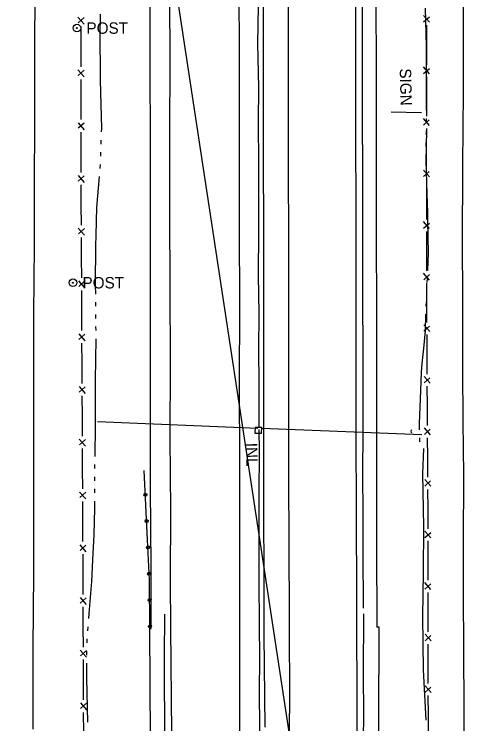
# Model space of a CAD drawing. Extents: x 589250 to 1188077, y 162953 to 363065.
# Drawn here: x 593915.1 to 594159.9, y 176311.4 to 176684.2 of the extents above; entities that cross this region are included whole.
import ezdxf

# ---------------------------------------------------------------- set-up
doc = ezdxf.new("R2010")
doc.units = 0
for name, color, linetype in [('E_BMGRD_P', 7, 'Continuous'), ('E_DRN', 7, 'Continuous'), ('E_DRN_Pipe', 7, 'Continuous'), ('E_DRN_SS_UG', 7, 'Continuous'), ('E_DRN_Text', 7, 'Continuous'), ('E_FEN_P', 7, 'Continuous'), ('E_MISCPROP', 7, 'Continuous'), ('E_RDWY', 7, 'Continuous'), ('E_RDWY_Gravel', 7, 'Continuous'), ('E_SGN', 7, 'Continuous'), ('E_SGN_Text', 7, 'Continuous'), ('E_WAL', 7, 'Continuous'), ('E_WTR_FlowLine', 7, 'Continuous')]:
    doc.layers.add(name, color=color, linetype=linetype)

msp = doc.modelspace()

# ---------------------------------------------------------------- linework, layer by layer
at = {"layer": 'E_BMGRD_P'}
for p, q in [((593985.24, 176408.17), (593983.43, 176444.48)), ((593986.13, 176387.05), (593985.24, 176408.17)), ((593986.43, 176361.44), (593986.13, 176387.05))]:
    msp.add_line(p, q, dxfattribs=at)
for centre, major_axis, ratio in [((593984.06, 176431.8), (0.049, -0.805), 0.932546), ((593984.06, 176431.8), (0.025, -0.406), 0.932546), ((593984.75, 176417.97), (0.049, -0.805), 0.932546), ((593984.75, 176417.97), (0.025, -0.406), 0.932546), ((593985.41, 176404.13), (0.054, -0.805), 0.93253), ((593985.41, 176404.13), (0.027, -0.406), 0.93253), ((593985.99, 176390.29), (0.054, -0.805), 0.93253), ((593985.99, 176390.29), (0.027, -0.406), 0.93253), ((593986.25, 176376.45), (0.051, -0.805), 0.932542), ((593986.25, 176376.45), (0.025, -0.406), 0.932542), ((593986.42, 176362.6), (0.051, -0.805), 0.932542), ((593986.42, 176362.6), (0.025, -0.406), 0.932542)]:
    msp.add_ellipse(centre, major_axis=major_axis, ratio=ratio, dxfattribs=at)
at = {"layer": 'E_DRN'}
for p, q in [((594041.72, 176467.16), (594041.59, 176464.19)), ((594045.23, 176467.01), (594041.72, 176467.16)), ((594045.1, 176464.05), (594045.23, 176467.01)), ((594041.59, 176464.19), (594045.1, 176464.05))]:
    msp.add_line(p, q, dxfattribs=at)
msp.add_arc((594124.58, 176465.03), 0.951, 123.209, 229.4692, dxfattribs=at)
at = {"layer": 'E_DRN_Pipe'}
msp.add_line((594159.86, 175649.53), (593883.52, 177463.68), dxfattribs=at)
for points in [[(594097.87, 176869.17), (594097.7, 176846.21), (594097.91, 176822.26), (594097.93, 176797.28), (594097.77, 176779.42), (594097.83, 176761.39), (594097.7, 176742.5), (594097.95, 176721.78), (594098.08, 176697.67), (594098.04, 176672.95), (594097.93, 176651.09), (594097.96, 176628.52), (594098.17, 176602.72), (594098.15, 176579.66), (594098.22, 176557.12), (594098.25, 176534.43), (594098.28, 176507.45), (594098.28, 176487.3), (594098.37, 176465.05), (594098.21, 176442.71), (594098.39, 176421.74), (594098.44, 176402.02), (594098.56, 176372.17)], [(594042.61, 176764.33), (594042.66, 176762.08), (594042.86, 176743.94), (594043.31, 176721.62), (594043.28, 176707.53), (594043.36, 176688.63), (594042.95, 176668.69), (594043.52, 176645.78), (594043.25, 176627.63), (594043.48, 176605.24), (594043.45, 176590.6), (594043.51, 176570.12), (594043.26, 176547.09), (594043.67, 176526.6), (594043.49, 176508.41), (594043.6, 176489.67), (594043.62, 176471.63), (594043.67, 176467.31)], [(593994.11, 176369), (593993.98, 176346.56), (593993.99, 176331.82), (593994.17, 176314.67), (593994.25, 176292.54), (593994.15, 176275.69), (593994.42, 176254.71), (593994.42, 176231.83), (593994.49, 176213.17), (593994.3, 176195.64), (593994.4, 176168.84), (593994.74, 176145.96), (593994.45, 176124.58), (593994.62, 176098.63), (593994.59, 176075.14), (593994.15, 176056.15), (593994.89, 176029.41), (593994.77, 176002.81)], [(594098.63, 176369.17), (594098.56, 176337.66), (594098.72, 176316.3), (594098.38, 176289.66), (594098.8, 176267.67), (594098.77, 176247.92), (594098.81, 176225.2), (594098.76, 176203.17), (594098.75, 176181.09), (594098.75, 176158.95), (594098.97, 176132.32), (594098.97, 176114.04), (594099.06, 176093.75), (594099.1, 176076.01), (594098.98, 176058.16), (594099.23, 176036.17)]]:
    msp.add_lwpolyline(points, dxfattribs=at)
at = {"layer": 'E_DRN_SS_UG'}
for p, q in [((594043.09, 176466.6), (593958.87, 176470.03)), ((594129.31, 176463.19), (594045.09, 176466.62))]:
    msp.add_line(p, q, dxfattribs=at)
msp.add_lwpolyline([(594043.68, 176466.02), (594043.81, 176454.35), (594043.61, 176431.93), (594043.68, 176409.33), (594043.62, 176386.16), (594043.86, 176363.78), (594043.96, 176345.88), (594043.8, 176328), (594043.97, 176309.66), (594044, 176291.49), (594043.78, 176268.84), (594043.9, 176218.3), (594043.83, 176199.66), (594044.05, 176176.8), (594043.89, 176156.39), (594043.91, 176137.72), (594044.02, 176118.48), (594044.18, 176091.52), (594044.19, 176072.96), (594044.24, 176067.55)], dxfattribs=at)
at = {"layer": 'E_FEN_P'}
for p, q in [((593948.58, 176682.63), (593951.8, 176678.94)), ((593951.79, 176682.46), (593948.65, 176679.68)), ((594133.44, 176679.98), (594130.3, 176683.58)), ((594130.3, 176680.14), (594133.38, 176682.85)), ((593950.07, 176677.71), (593950.08, 176667.12)), ((594131.98, 176668.04), (594131.99, 176678.39)), ((593950.08, 176667.12), (593950.09, 176656.54)), ((594131.97, 176657.7), (594131.98, 176668.04)), ((594130.27, 176653.06), (594133.35, 176655.77)), ((594133.41, 176652.89), (594130.28, 176656.5)), ((593948.61, 176654.91), (593951.83, 176651.23)), ((593951.82, 176654.75), (593948.68, 176651.97)), ((593950.1, 176649.99), (593950.11, 176639.41)), ((594131.95, 176640.96), (594131.96, 176651.3)), ((594131.94, 176630.62), (594131.95, 176640.96)), ((593950.11, 176639.41), (593950.12, 176628.83)), ((594133.38, 176625.8), (594130.25, 176629.41)), ((593948.64, 176627.2), (593951.86, 176623.52)), ((593951.85, 176627.04), (593948.71, 176624.26)), ((594130.25, 176625.97), (594133.32, 176628.68)), ((593950.13, 176622.28), (593950.14, 176611.7)), ((594131.92, 176613.87), (594131.93, 176624.21)), ((593950.14, 176611.7), (593950.15, 176601.12)), ((594131.91, 176606.05), (594131.92, 176613.87)), ((594131.92, 176603.53), (594131.91, 176606.05)), ((593948.67, 176599.49), (593951.89, 176595.81)), ((593951.88, 176599.32), (593948.74, 176596.55)), ((594133.38, 176598.72), (594130.23, 176602.32)), ((594130.24, 176598.88), (594133.31, 176601.6)), ((594131.95, 176586.79), (594131.93, 176597.13)), ((593950.16, 176594.57), (593950.17, 176590)), ((593950.17, 176590), (593950.19, 176583.99)), ((594131.97, 176576.44), (594131.95, 176586.79)), ((593950.19, 176583.99), (593950.24, 176573.41)), ((594133.43, 176571.64), (594130.29, 176575.23)), ((594130.3, 176571.79), (594133.36, 176574.51)), ((593948.77, 176571.77), (593952, 176568.1)), ((593951.98, 176571.62), (593948.85, 176568.83)), ((594132.01, 176559.7), (594131.99, 176570.04)), ((593950.27, 176566.86), (593950.32, 176556.28)), ((594132.03, 176549.36), (594132.01, 176559.7)), ((593950.32, 176556.28), (593950.37, 176545.7)), ((594133.49, 176544.55), (594130.34, 176548.15)), ((594130.35, 176544.71), (594133.42, 176547.42)), ((593948.9, 176544.06), (593952.12, 176540.39)), ((593952.11, 176543.91), (593948.98, 176541.12)), ((594132.06, 176532.61), (594132.04, 176542.96)), ((593950.4, 176539.15), (593950.45, 176528.57)), ((594132.08, 176522.27), (594132.06, 176532.61)), ((593950.45, 176528.57), (593950.5, 176517.98)), ((594133.54, 176517.46), (594130.4, 176521.06)), ((594130.41, 176517.62), (594133.47, 176520.34)), ((593949.03, 176516.35), (593952.25, 176512.68)), ((593952.24, 176516.2), (593949.11, 176513.41)), ((594132.17, 176505.53), (594132.1, 176515.87)), ((593950.53, 176511.43), (593950.58, 176500.85)), ((594132.23, 176495.19), (594132.17, 176505.53)), ((593950.58, 176500.85), (593950.63, 176490.27)), ((594133.71, 176490.38), (594130.55, 176493.97)), ((594130.57, 176490.53), (594133.63, 176493.26)), ((593949.16, 176488.64), (593952.38, 176484.97)), ((593952.37, 176488.48), (593949.24, 176485.7)), ((594132.33, 176478.44), (594132.27, 176488.78)), ((593950.66, 176483.72), (593950.72, 176473.14)), ((594132.4, 176468.1), (594132.33, 176478.44)), ((593950.72, 176473.14), (593950.77, 176462.56)), ((594133.87, 176463.3), (594130.72, 176466.88)), ((594130.74, 176463.44), (594133.79, 176466.17)), ((594132.5, 176451.36), (594132.44, 176461.7)), ((593949.3, 176460.93), (593952.53, 176457.26)), ((593952.51, 176460.77), (593949.38, 176457.98)), ((593950.81, 176456.01), (593950.86, 176445.43)), ((594132.56, 176441.01), (594132.5, 176451.36)), ((593950.86, 176445.43), (593950.92, 176434.85)), ((594134.04, 176436.21), (594130.88, 176439.79)), ((594130.9, 176436.36), (594133.96, 176439.09)), ((593949.44, 176433.21), (593952.67, 176429.54)), ((593952.65, 176433.06), (593949.52, 176430.27)), ((594132.66, 176424.42), (594132.6, 176434.61)), ((593950.95, 176428.3), (593951.01, 176417.72)), ((594132.66, 176424.27), (594132.66, 176424.42)), ((594132.68, 176413.93), (594132.66, 176424.27)), ((593951.01, 176417.72), (593951.06, 176407.14)), ((594134.13, 176409.12), (594130.99, 176412.72)), ((594131, 176409.28), (594134.06, 176411.99)), ((593949.59, 176405.5), (593952.82, 176401.83)), ((594132.7, 176397.18), (594132.69, 176407.53)), ((593952.8, 176405.35), (593949.67, 176402.56)), ((593951.09, 176400.59), (593951.1, 176399.47)), ((593951.1, 176399.47), (593951.14, 176390.01)), ((594132.71, 176386.84), (594132.7, 176397.18)), ((593951.14, 176390.01), (593951.17, 176379.43)), ((594134.17, 176382.03), (594131.03, 176385.63)), ((594131.03, 176382.19), (594134.1, 176384.91)), ((594132.73, 176370.1), (594132.72, 176380.44)), ((593949.7, 176377.79), (593952.92, 176374.12)), ((593952.91, 176377.64), (593949.78, 176374.85)), ((593951.2, 176372.88), (593951.24, 176362.3)), ((594132.75, 176359.75), (594132.73, 176370.1)), ((593951.24, 176362.3), (593951.28, 176351.71)), ((594134.2, 176354.95), (594131.06, 176358.54)), ((594131.07, 176355.11), (594134.13, 176357.82)), ((594132.77, 176343.01), (594132.76, 176353.35)), ((593949.8, 176350.08), (593953.02, 176346.41)), ((593953.01, 176349.92), (593949.88, 176347.14)), ((593951.3, 176345.16), (593951.34, 176334.58)), ((594132.78, 176332.67), (594132.77, 176343.01)), ((593951.34, 176334.58), (593951.38, 176324)), ((594134.24, 176327.86), (594131.1, 176331.46)), ((594131.1, 176328.02), (594134.17, 176330.73)), ((594132.8, 176315.92), (594132.79, 176326.27)), ((593949.9, 176322.37), (593953.13, 176318.7)), ((593953.11, 176322.21), (593949.98, 176319.43)), ((593951.4, 176317.45), (593951.44, 176306.87)), ((594132.88, 176305.22), (594132.8, 176315.92))]:
    msp.add_line(p, q, dxfattribs=at)
at = {"layer": 'E_MISCPROP'}
for centre, radius in [((593948.07, 176676.92), 2), ((593948.07, 176676.92), 0.25), ((593945.98, 176543.14), 2), ((593945.98, 176543.14), 0.25)]:
    msp.add_circle(centre, radius, dxfattribs=at)
at = {"layer": 'E_RDWY'}
for p, q in [((594094.72, 176678.3), (594094.79, 176715.51)), ((594151.37, 176680.04), (594151.06, 176711.69)), ((594059.04, 176710.25), (594059.11, 176678.18)), ((593925.93, 176704.88), (593925.81, 176668.59)), ((593996.69, 176703.87), (593996.86, 176660.28)), ((594033.47, 176667.78), (594033.33, 176705.48)), ((594059.11, 176678.18), (594059.18, 176644.18)), ((594094.72, 176650.65), (594094.72, 176678.3)), ((594151.33, 176643.35), (594151.37, 176680.04)), ((593925.81, 176668.59), (593925.75, 176628.81)), ((594033.55, 176640.96), (594033.47, 176667.78)), ((593996.86, 176660.28), (593996.77, 176620.96)), ((594094.75, 176620.73), (594094.72, 176650.65)), ((594059.18, 176644.18), (594059.16, 176604.61)), ((594033.5, 176605.56), (594033.55, 176640.96)), ((594150.9, 176604.91), (594151.33, 176643.35)), ((593925.75, 176628.81), (593925.59, 176592.83)), ((593996.77, 176620.96), (593996.79, 176579.16)), ((594094.8, 176581.19), (594094.75, 176620.73)), ((594033.57, 176569.35), (594033.5, 176605.56)), ((594059.16, 176604.61), (594059.28, 176564.54)), ((594150.75, 176562.75), (594150.9, 176604.91)), ((593925.59, 176592.83), (593925.49, 176562.44)), ((594094.82, 176547.11), (594094.8, 176581.19)), ((593996.79, 176579.16), (593996.93, 176541.44)), ((594033.62, 176534.08), (594033.57, 176569.35)), ((593925.49, 176562.44), (593925.3, 176526.55)), ((594059.28, 176564.54), (594059.31, 176524.57)), ((594150.97, 176536.54), (594150.75, 176562.75)), ((594094.81, 176505.47), (594094.82, 176547.11)), ((593996.93, 176541.44), (593997.05, 176500.11)), ((594151.01, 176497.96), (594150.97, 176536.54)), ((594033.55, 176486.69), (594033.62, 176534.08)), ((593925.3, 176526.55), (593925.26, 176492.28)), ((594059.31, 176524.57), (594059.34, 176479.92)), ((594094.94, 176461.06), (594094.81, 176505.47)), ((593997.05, 176500.11), (593996.93, 176461.98)), ((594151.06, 176470.32), (594151.01, 176497.96)), ((593925.26, 176492.28), (593925.24, 176461.33)), ((594033.64, 176451.04), (594033.55, 176486.69)), ((594059.34, 176479.92), (594059.32, 176444.41)), ((594151.47, 176442.3), (594151.06, 176470.32)), ((593925.24, 176461.33), (593925.25, 176429.68)), ((593996.93, 176461.98), (593997.16, 176423.53)), ((594095.04, 176425.48), (594094.94, 176461.06)), ((594033.69, 176414.13), (594033.64, 176451.04)), ((594059.32, 176444.41), (594059.47, 176402.42)), ((594151.35, 176405.96), (594151.47, 176442.3)), ((593925.25, 176429.68), (593925.17, 176390.52)), ((594095.17, 176374.5), (594095.04, 176425.48)), ((593997.16, 176423.53), (593997.09, 176386.83)), ((594033.7, 176366.21), (594033.69, 176414.13)), ((594151.34, 176382.04), (594151.35, 176405.96)), ((594059.47, 176402.42), (594059.57, 176370.43)), ((593925.17, 176390.52), (593924.91, 176351.18)), ((593997.09, 176386.83), (593997.27, 176361.75)), ((594151.54, 176348.43), (594151.34, 176382.04)), ((594095.42, 176314.73), (594095.17, 176374.5)), ((594059.57, 176370.43), (594059.75, 176316.94)), ((594033.71, 176315.56), (594033.7, 176366.21)), ((593997.27, 176361.75), (593997.7, 176306.33)), ((593924.91, 176351.18), (593924.91, 176308.55)), ((594151.71, 176321.24), (594151.54, 176348.43)), ((594151.65, 176293.92), (594151.71, 176321.24)), ((594059.83, 176289.72), (594059.75, 176316.94)), ((594033.78, 176289.17), (594033.71, 176315.56)), ((594095.42, 176268.55), (594095.42, 176314.73))]:
    msp.add_line(p, q, dxfattribs=at)
at = {"layer": 'E_RDWY_Gravel'}
for p, q in [((594105.17, 176693.47), (594105.34, 176654.08)), ((593986.64, 176654.73), (593986.52, 176691.85)), ((593986.66, 176618.68), (593986.64, 176654.73)), ((594105.34, 176654.08), (594105.34, 176613.32)), ((593986.71, 176581.26), (593986.66, 176618.68)), ((594105.34, 176613.32), (594105.37, 176570.08)), ((593986.78, 176544.82), (593986.71, 176581.26)), ((594105.37, 176570.08), (594105.52, 176526.27)), ((593986.76, 176505.35), (593986.78, 176544.82)), ((594105.52, 176526.27), (594105.5, 176486.68)), ((593986.81, 176469.75), (593986.76, 176505.35)), ((594105.5, 176486.68), (594105.54, 176447.38)), ((593986.8, 176435.15), (593986.81, 176469.75)), ((594105.54, 176447.38), (594105.61, 176405.81)), ((593987.01, 176394.13), (593986.8, 176435.15)), ((594105.61, 176405.81), (594105.68, 176362.25)), ((593987.06, 176361.44), (593987.01, 176394.13))]:
    msp.add_line(p, q, dxfattribs=at)
at = {"layer": 'E_SGN'}
msp.add_line((594113.32, 176632.89), (594129.24, 176632.57), dxfattribs=at)
at = {"layer": 'E_WAL'}
for p, q in [((594046.16, 176658.09), (594046.05, 176724.28)), ((594046.18, 176621.84), (594046.16, 176658.09)), ((594046.27, 176557.98), (594046.18, 176621.84)), ((594046.32, 176518.91), (594046.27, 176557.98)), ((594046.39, 176454.13), (594046.32, 176518.91)), ((594046.57, 176358.12), (594046.39, 176454.13)), ((593986.43, 176361.44), (593987.06, 176361.44)), ((593986.74, 176303.64), (593986.43, 176361.44)), ((594106.87, 176362.19), (594105.68, 176362.25)), ((594106.83, 176312.27), (594106.87, 176362.19)), ((594047.06, 176309.69), (594046.57, 176358.12)), ((594106.92, 176291.07), (594106.83, 176312.43))]:
    msp.add_line(p, q, dxfattribs=at)
at = {"layer": 'E_WTR_FlowLine'}
for p, q in [((594131.81, 176667.26), (594131.35, 176687.34)), ((593960.26, 176684.18), (593960.17, 176672.66)), ((593960.17, 176672.66), (593960.21, 176653.26)), ((594131.81, 176664.02), (594131.81, 176667.26)), ((594131.84, 176644.75), (594131.81, 176664.02)), ((593960.21, 176653.26), (593960.22, 176649.55)), ((593960.22, 176649.55), (593960.93, 176624.16)), ((594131.8, 176633.58), (594131.84, 176644.75)), ((594131.77, 176627.28), (594131.78, 176629.38)), ((593960.93, 176624.16), (593960.86, 176622.35)), ((594131.74, 176620.98), (594131.75, 176622.01)), ((594131.75, 176622.01), (594131.76, 176623.08)), ((593960.7, 176618.09), (593960.62, 176615.96)), ((594131.68, 176614.68), (594131.7, 176616.78)), ((593960.45, 176611.7), (593960.37, 176609.57)), ((594131.61, 176607.37), (594131.64, 176610.49)), ((594132.21, 176589.82), (594131.61, 176607.37)), ((593960.21, 176605.31), (593960.13, 176603.17)), ((593959.74, 176598.93), (593958.26, 176582.59)), ((594132.46, 176580.06), (594132.21, 176589.82)), ((593958.26, 176582.59), (593957.93, 176568.08)), ((594132.57, 176575.56), (594132.46, 176580.06)), ((594132.96, 176558.89), (594132.57, 176575.56)), ((593957.93, 176568.08), (593957.8, 176562.52)), ((593957.8, 176562.52), (593957.71, 176542.02)), ((594132.54, 176549.63), (594132.96, 176558.89)), ((594132.26, 176543.41), (594132.36, 176545.44)), ((594132.26, 176543.34), (594132.26, 176543.41)), ((593957.71, 176542.02), (593957.75, 176537.16)), ((594131.98, 176537.05), (594132.07, 176539.14)), ((593957.79, 176532.9), (593957.8, 176530.77)), ((594131.7, 176530.97), (594131.79, 176532.85)), ((594131.7, 176530.76), (594131.7, 176530.97)), ((593957.84, 176526.5), (593957.86, 176524.37)), ((594131.28, 176517.94), (594131.56, 176526.56)), ((593957.9, 176520.1), (593957.92, 176517.97)), ((594130.45, 176508.52), (594131.28, 176517.94)), ((593957.95, 176513.71), (593957.61, 176491.9)), ((594129.5, 176500.74), (594130.45, 176508.52)), ((594129.27, 176496.23), (594129.5, 176500.74)), ((594128.78, 176486.53), (594129.27, 176496.22)), ((593957.61, 176491.9), (593957.62, 176482.79)), ((594128.13, 176469.2), (594128.78, 176486.53)), ((593957.62, 176482.79), (593957.64, 176467.89)), ((594128.19, 176465.81), (594128.13, 176469.2)), ((593957.64, 176467.89), (593957.42, 176451.87)), ((594128.3, 176459.51), (594128.26, 176461.61)), ((593957.37, 176447.61), (593957.34, 176445.48)), ((593957.28, 176441.21), (593957.25, 176439.08)), ((593957.23, 176434.82), (593957.23, 176432.69)), ((593957.23, 176428.42), (593957.22, 176424.52)), ((593957.22, 176424.52), (593957.01, 176410.77)), ((593957.01, 176410.77), (593956.3, 176397.53)), ((593956.3, 176397.53), (593955.69, 176386.22)), ((593955.69, 176386.22), (593954.34, 176369.47)), ((593954.34, 176369.47), (593954.12, 176366.69)), ((593953.78, 176362.44), (593953.61, 176360.31)), ((593953.27, 176356.06), (593953.18, 176355.02)), ((593953.18, 176355.02), (593953.18, 176353.93)), ((593953.15, 176349.67), (593953.14, 176347.53)), ((593953.12, 176343.27), (593953.07, 176335.16)), ((593953.07, 176335.16), (593953.54, 176312.36))]:
    msp.add_line(p, q, dxfattribs=at)
msp.add_lwpolyline([(594131.67, 176313.33), (594130.26, 176339.85), (594129.99, 176367.68), (594130.19, 176391.06), (594130.46, 176414.85), (594129.9, 176442.84), (594130.38, 176455.99)], dxfattribs=at)

# ---------------------------------------------------------------- texts
at = {"layer": 'E_DRN_Text'}
msp.add_text('INL', height=6, rotation=271.3088, dxfattribs=at).set_placement((594036.88, 176459))
at = {"layer": 'E_MISCPROP'}
for p in [(593953.07, 176673.92), (593950.99, 176540.14)]:
    msp.add_text('POST', height=6, dxfattribs=at).set_placement(p)
at = {"layer": 'E_SGN_Text'}
msp.add_text('SIGN', height=6, rotation=271.3088, dxfattribs=at).set_placement((594117.76, 176655.7))

doc.saveas('drawing.dxf')
